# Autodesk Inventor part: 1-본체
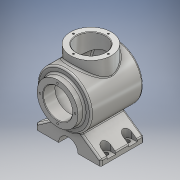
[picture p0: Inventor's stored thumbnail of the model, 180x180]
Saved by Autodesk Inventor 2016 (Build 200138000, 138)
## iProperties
Created: 2017-04
Part Number: 1-본체
Material: 알루미늄 6061
Document SubType Name: Modeling
Designer: SMW
Density: 2.7 g/cm^3
Appearance: 알루미늄 - 평지
Mass: 1664.52 g
Surface Area: 1066.89 cm^2
Volume: 616.49 cm^3
Author: SMW
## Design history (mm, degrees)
sketch "스케치1"
  geometry: L1 (-62, 0)-(-50, 0); L2 (-50, 0)-(-50, 38); L3 (-50, 38)-(-62, 38); L4 (-62, 38)-(-62, 0); L5 (-50, 0)-(58, 0); L6 (58, 0)-(58, 50); L7 (58, 50)-(-50, 50); L8 (-50, 50)-(-50, 0); A1 r 113 centre (-55, 0) between (58, 0) and (46.336, 50); 1 further point
  constraints: 16 end point, 4 parallel, 2 horizontal, 2 perpendicular, 2 point on circle, 2 point on line, 1 centre point, 1 tangent
  dimensions: "d0" = 108 distance of L6.end L7.end; "d1" = 12 distance of L2.end L3.end; "d2" = 76 diameter of L3 L5; "d3" = 100 diameter of L7 L5; "d4" = 113 radius of A1; "d5" = 50 distance from line of point (0, 0) L8
revolve "회전1" sketch "스케치1" stored, may be unused: angle "d6" = 90 deg
sketch "스케치2"
  geometry: C1 r 38 at (0, 0); 1 further point
  constraints: 1 centre point, 1 coincident
  dimensions: "d7" = 76 diameter of C1
extrude "돌출1" join sketch "스케치2" distance "d8" = 65; taper "d9" = 0 deg
sketch "스케치3"
  geometry: L1 (60, -82)-(-60, -82); L2 (-60, -82)-(-60, -72); L3 (-60, -72)-(-21.584, -45.101); L4 (60, -82)-(60, -72); L5 (60, -72)-(21.584, -45.101); A1 r 50 centre (0, 0) between (-21.584, -45.101) and (21.584, -45.101) reference; 2 further points
  constraints: 10 end point, 2 equal length, 2 point on circle, 1 horizontal, 1 midpoint, 1 perpendicular, 1 vertical, 1 vertical alignment
  dimensions: "d10" = 10 distance of L1.end L2.end; "d11" = 120 distance of L1.start L1.end; "d14" = 82 distance from line of L1 point (0, 0); "d15" = 55 deg angle of L3 L2
sketch "스케치4"
  geometry: L1 (-42, 0)-(38, 0); L2 (38, 0)-(38, -82); L3 (38, -82)-(-42, -82); L4 (-42, -82)-(-42, 0); L5 (-50, -50)-(-50, 50) reference; 1 further point
  constraints: 8 end point, 2 parallel, 1 horizontal, 1 perpendicular, 1 point on line
  dimensions: "d16" = 8 distance between parallel lines of L4 L5; "d17" = 80 distance of L2.end L3.end; "d18" = 82 distance of L1.end L2.end; "d19" = 42 distance from line of point (0, 0) L4 (derived); "d20" = 38 distance from line of point (0, 0) L2 (derived)
extrude "돌출2" join sketch "스케치3" distance "d21" = 38; taper "d23" = 0 deg; dims "d22" = 42, "d24" = 0
node "작업 평면1"
sketch "스케치5"
  geometry: L1 (10, -20)-(110, -20); L2 (110, -20)-(110, -60); L3 (110, -60)-(10, -60); L4 (10, -60)-(10, -20); L5 (10, -20)-(110, -60); L6 (110, -20)-(10, -60); L7 (130, -60)-(110, -60); L8 (120, 0)-(120, -80) reference; L9 (130, -52)-(110, -52); L10 (110, -68)-(130, -68); L11 (130, -20)-(110, -20); L12 (130, -28)-(110, -28); L13 (110, -12)-(130, -12); L14 (-10, -60)-(10, -60); L15 (0, -80)-(0, 0) reference; L16 (-10, -68)-(10, -68); L17 (10, -52)-(-10, -52); L18 (-10, -20)-(10, -20); L19 (-10, -28)-(10, -28); L20 (10, -12)-(-10, -12); L21 (120, -80)-(0, -80) reference; A1 r 8 centre (130, -60) between (130, -68) and (130, -52); A2 r 8 centre (110, -60) between (110, -52) and (110, -68); A3 r 8 centre (130, -20) between (130, -28) and (130, -12); A4 r 8 centre (110, -20) between (110, -12) and (110, -28); A5 r 8 centre (-10, -60) between (-10, -52) and (-10, -68); A6 r 8 centre (10, -60) between (10, -68) and (10, -52); A7 r 8 centre (-10, -20) between (-10, -12) and (-10, -28); A8 r 8 centre (10, -20) between (10, -28) and (10, -12); 5 further points
  constraints: 44 end point, 16 point on circle, 16 tangent, 8 centre point, 6 parallel, 6 point on line, 5 perpendicular, 4 midpoint, 3 equal radius, 1 horizontal
  dimensions: "d28" = 8 radius of A2; "d117" = 10 distance from line of L8 L2.end; "d118" = 20 distance between parallel lines of L21 L3; "d119" = 40 distance of L1.end L2.end; "d120" = 100 distance of L1.start L1.end
extrude "돌출3" cut sketch "스케치5" distance "d29" = 38; taper "d30" = 0 deg
hole "구멍1" diameter "d33" = 8; stored, may be unused: countersink angle "d37" = 90 deg, drill point angle "d39" = 118 deg; dims "d31" = 10, "d32" = 10, "d34" = 6, "d35" = 4, "d36" = 2, "d38" = 8
hole "구멍2" diameter "d42" = 8; stored, may be unused: countersink angle "d46" = 90 deg, drill point angle "d48" = 118 deg; dims "d40" = 10, "d41" = 10, "d43" = 6, "d44" = 4, "d45" = 2, "d47" = 8
hole "구멍3" diameter "d51" = 8; stored, may be unused: countersink angle "d55" = 90 deg, drill point angle "d57" = 118 deg; dims "d49" = 10, "d50" = 10, "d52" = 6, "d53" = 4, "d54" = 2, "d56" = 8
hole "구멍4" diameter "d60" = 8; stored, may be unused: countersink angle "d64" = 90 deg, drill point angle "d66" = 118 deg; dims "d58" = 10, "d59" = 10, "d61" = 6, "d62" = 4, "d63" = 2, "d65" = 8
sketch "스케치6"
  geometry: 2 further points
hole "구멍5" sketch "스케치6" at (0, -82) diameter "d67" = 36; stored, may be unused: countersink angle "d71" = 90 deg, drill point angle "d73" = 118 deg; dims "d68" = 6, "d69" = 4, "d70" = 2, "d72" = 8
hole "구멍6" diameter "d76" = 54; stored, may be unused: countersink angle "d80" = 90 deg, drill point angle "d82" = 0 deg; dims "d74" = 10, "d75" = 10, "d77" = 6, "d78" = 4, "d79" = 2, "d81" = 8
sketch "스케치7"
  geometry: L1 (-50, 50)-(46.336, 50) reference; L2 (-50, -50)-(46.336, -50) reference; L3 (-50, -50)-(-50, 50) reference; L4 (-62, 38)-(-50, 38) reference; L5 (-62, -38)-(-50, -38) reference; L6 (48, 0)-(-40, 0); L7 (-40, 0)-(-40, 40); L8 (-40, 40)-(48, 40); L9 (48, 40)-(48, 0); L10 (-62, -38)-(-62, 38) reference; L11 (-40, 0)-(-62, 0); L12 (-62, 0)-(-62, 27); L13 (-62, 27)-(-40, 27); L14 (-40, 27)-(-40, 0); A1 r 113 centre (-55, 0) between (46.336, -50) and (46.336, 50) reference; A2 r 103 centre (-55, 0) between (39.916, -40) and (39.916, 40); 2 further points
  constraints: 16 end point, 4 parallel, 3 point on circle, 2 horizontal, 2 perpendicular, 2 point on line, 1 centre point, 1 coincident, 1 collinear
  dimensions: "d83" = 10 radial gap between concentric circles of A1 A2; "d84" = 40 distance between parallel lines of L6 L8; "d85" = 22 distance between parallel lines of L10 L7; "d86" = 27 distance between parallel lines of L11 L13
revolve "회전2" sketch "스케치7" stored, may be unused: angle "d87" = 90 deg
sketch "스케치8"
  geometry: L1 (0, 0)-(0, 32.5)
  constraints: 2 end point, 1 vertical
  dimensions: "d88" = 32.5 distance of L1.start L1.end
hole "구멍7" sketch "스케치8" at (0, 32.5) diameter "d89" = 3.242; stored, may be unused: countersink angle "d93" = 90 deg, drill point angle "d95" = 118 deg; dims "d90" = 8, "d91" = 4, "d92" = 2, "d94" = 10
sketch "스케치9"
  geometry: L1 (0, 0)-(0, 32.5)
  constraints: 2 end point, 1 vertical
  dimensions: "d99" = 32.5 distance of L1.start L1.end
hole "구멍8" sketch "스케치9" at (0, 32.5) diameter "d100" = 3.242; stored, may be unused: countersink angle "d104" = 90 deg, drill point angle "d106" = 118 deg; dims "d101" = 8, "d102" = 4, "d103" = 2, "d105" = 10
node "작업 평면2"
sketch "스케치10"
  geometry: 2 further points
  constraints: 1 coincident, 1 other
feature "엠보싱1" sketch "스케치10" dims "d0" = 108, "d1" = 12, "d2" = 76, "d3" = 100, "d4" = 113, "d5" = 50, "d10" = 10, "d11" = 120, "d14" = 82, "d15" = 55 deg, "d110" = 0.5, "d111" = 0
chamfer "모따기1" distance "d112" = 1; stored, may be unused: second distance "d113" = 2, angle "d114" = 45 deg
fillet "모깎기1" dims "d115" = 3
fillet "모깎기2" dims "d116" = 3
node "솔리드1"
pattern_circular "원형 패턴1" dims angle "d97" = 360 deg
pattern_circular "원형 패턴2" dims angle "d108" = 360 deg
other parameters: "d25" = -6
